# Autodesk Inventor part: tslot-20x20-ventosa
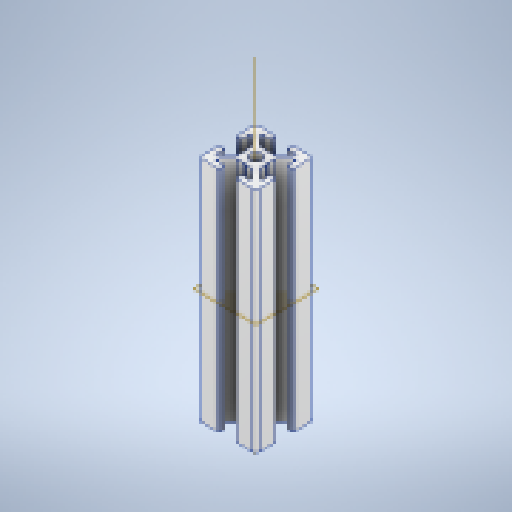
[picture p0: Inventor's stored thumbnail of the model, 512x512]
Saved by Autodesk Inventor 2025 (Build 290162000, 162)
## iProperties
Created: 2025-03
Part Number: tslot-20x20-ventosa
Material: Alluminio 6061
Document SubType Name: Modeling
Designer: Ryzen5700u
Density: 2.7 g/cm^3
Appearance: Alluminio - Piatto
Author: Ryzen5700u
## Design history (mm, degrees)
feature "Base1"
sketch "Schizzo1"
  geometry: L1 (3.761, -16)-(4.7, -16) reference; L2 (3.761, -16)-(0.7, -12.939) reference; L3 (0.7, -12.939)-(0.7, -10.52) reference; L4 (0.4, -10)-(0.7, -10.52) reference; L5 (0.4, -10)-(0.7, -9.48) reference; L6 (0.7, -7.061)-(0.7, -9.48) reference; L7 (3.761, -4)-(0.7, -7.061) reference; L8 (3.761, -4)-(4.7, -4) reference; L9 (4.7, -4)-(4.7, -7) reference; L10 (4.7, -7)-(6.4, -7) reference; L11 (6.7, -6.7)-(6.7, -1) reference; L12 (5.7, 0)-(0, 0) reference; L13 (-0.3, -2)-(-0.3, -0.3) reference; L14 (2.7, -2)-(-0.3, -2) reference; L15 (2.7, -2.939)-(2.7, -2) reference; L16 (2.7, -2.939)-(-0.361, -6) reference; L17 (-0.361, -6)-(-2.78, -6) reference; L18 (-3.3, -6.3)-(-2.78, -6) reference; L19 (-3.3, -6.3)-(-3.82, -6) reference; L20 (-6.239, -6)-(-3.82, -6) reference; L21 (-9.3, -2.939)-(-6.239, -6) reference; L22 (-9.3, -2.939)-(-9.3, -2) reference; L23 (-9.3, -2)-(-6.3, -2) reference; L24 (-6.3, -2)-(-6.3, -0.3) reference; L25 (-12.3, 0)-(-6.6, 0) reference; L26 (-13.3, -6.7)-(-13.3, -1) reference; L27 (-11.3, -7)-(-13, -7) reference; L28 (-11.3, -4)-(-11.3, -7) reference; L29 (-10.361, -4)-(-11.3, -4) reference; L30 (-10.361, -4)-(-7.3, -7.061) reference; L31 (-7.3, -7.061)-(-7.3, -9.48) reference; L32 (-7, -10)-(-7.3, -9.48) reference; L33 (-7, -10)-(-7.3, -10.52) reference; L34 (-7.3, -12.939)-(-7.3, -10.52) reference; L35 (-10.361, -16)-(-7.3, -12.939) reference; L36 (-10.361, -16)-(-11.3, -16) reference; L37 (-11.3, -16)-(-11.3, -13) reference; L38 (-11.3, -13)-(-13, -13) reference; L39 (-13.3, -13.3)-(-13.3, -19) reference; L40 (-12.3, -20)-(-6.6, -20) reference; L41 (-6.3, -18)-(-6.3, -19.7) reference; L42 (-9.3, -18)-(-6.3, -18) reference; L43 (-9.3, -17.061)-(-9.3, -18) reference; L44 (-9.3, -17.061)-(-6.239, -14) reference; L45 (-6.239, -14)-(-3.82, -14) reference; L46 (-3.3, -13.7)-(-3.82, -14) reference; L47 (-3.3, -13.7)-(-2.78, -14) reference; L48 (-0.361, -14)-(-2.78, -14) reference; L49 (2.7, -17.061)-(-0.361, -14) reference; L50 (2.7, -17.061)-(2.7, -18) reference; L51 (2.7, -18)-(-0.3, -18) reference; L52 (-0.3, -18)-(-0.3, -19.7) reference; L53 (5.7, -20)-(0, -20) reference; L54 (6.7, -13.3)-(6.7, -19) reference; L55 (4.7, -13)-(6.4, -13) reference; L56 (4.7, -16)-(4.7, -13) reference; C1 r 2.1 at (-3.3, -10) reference; A1 r 0.3 centre (6.4, -6.7) between (6.4, -7) and (6.7, -6.7) reference; A2 r 1 centre (5.7, -1) between (6.7, -1) and (5.7, 0) reference; A3 r 0.3 centre (0, -0.3) between (0, 0) and (-0.3, -0.3) reference; A4 r 0.3 centre (-6.6, -0.3) between (-6.3, -0.3) and (-6.6, 0) reference; A5 r 1 centre (-12.3, -1) between (-12.3, 0) and (-13.3, -1) reference; A6 r 0.3 centre (-13, -6.7) between (-13.3, -6.7) and (-13, -7) reference; A7 r 0.3 centre (-13, -13.3) between (-13, -13) and (-13.3, -13.3) reference; A8 r 1 centre (-12.3, -19) between (-13.3, -19) and (-12.3, -20) reference; A9 r 0.3 centre (-6.6, -19.7) between (-6.6, -20) and (-6.3, -19.7) reference; A10 r 0.3 centre (0, -19.7) between (-0.3, -19.7) and (0, -20) reference; A11 r 1 centre (5.7, -19) between (5.7, -20) and (6.7, -19) reference; A12 r 0.3 centre (6.4, -13.3) between (6.7, -13.3) and (6.4, -13) reference; 1 further point
extrude "Estrusione1" join sketch "Schizzo1" distance "d0" = 70; taper "d1" = 0 deg
node "Piano di lavoro1"
node "Asse di lavoro1"
node "Solido1"
node "Linea chiusa proiettata1"
